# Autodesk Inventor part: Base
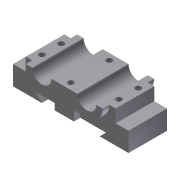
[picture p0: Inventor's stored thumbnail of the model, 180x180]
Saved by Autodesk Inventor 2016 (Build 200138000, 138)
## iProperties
Shininess: 77.0
Length Units: 11269
Angle Units: 11279
Time Units: 11290
Mass Units: 11283
Length Display Precision: 3
Angle Display Precision: 2
Created: 2002-02
Part Number: Base
Document SubType Name: Modeling
Designer: ***
Density: 1 g/cm^3
Material: Generic
Appearance: Default
Density: 0.0
Volumn: 0.0
Area: 0.0
PropertySet Name: Model Information
Control State: 0
Master: False
Checked Out: False
Author: ***
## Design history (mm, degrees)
sketch "Sketch2"
  geometry: L1 (-10.066, -1.263)-(24.934, -1.263); L2 (37.434, 11.237)-(32.434, 11.237); L3 (17.434, 11.237)-(-2.566, 11.237); L4 (-17.566, 11.237)-(-22.566, 11.237); A1 r 12.5 centre (-10.066, 11.237) between (-22.566, 11.237) and (-10.066, -1.263); A2 r 12.5 centre (24.934, 11.237) between (24.934, -1.263) and (37.434, 11.237); A3 r 7.5 centre (24.934, 11.237) between (17.434, 11.237) and (32.434, 11.237); A4 r 7.5 centre (-10.066, 11.237) between (-17.566, 11.237) and (-2.566, 11.237)
  constraints: 8 end point, 8 point on circle, 4 centre point, 3 horizontal, 3 parallel, 2 coincident, 2 equal radius, 2 tangent
  dimensions: "d0" = 12.5 radius of A1; "d1" = 7.5 radius of A4; "d2" = 35 distance of A1.centre A2.centre; "d3" = 12.5 distance between parallel lines of L3 L1
extrude "Extrusion1" new body sketch "Sketch2" stored distance "d4" = 40; taper "d5" = 0 deg
sketch "Sketch4"
  geometry: L1 (-27.566, 1.237)-(-37.566, 1.237); L2 (-37.566, 1.237)-(-37.566, -13.763); L3 (-37.566, -13.763)-(-15.066, -13.763); L4 (-15.066, -13.763)-(-20.066, -8.763); L5 (-20.066, -8.763)-(34.934, -8.763); L6 (34.934, -8.763)-(29.934, -13.763); L7 (29.934, -13.763)-(52.434, -13.763); L8 (52.434, -13.763)-(52.434, 1.237); L9 (52.434, 1.237)-(42.434, 1.237); L10 (24.934, -1.263)-(-10.066, -1.263); L11 (-17.566, 11.237)-(-22.566, 11.237) reference; L12 (37.434, 11.237)-(32.434, 11.237) reference; L13 (-22.566, 11.237)-(-27.566, 11.237); L14 (-27.566, 11.237)-(-27.566, 1.237); L15 (37.434, 11.237)-(42.434, 11.237); L16 (42.434, 11.237)-(42.434, 1.237); A1 r 12.5 centre (24.934, 11.237) between (24.934, -1.263) and (37.434, 11.237); A2 r 12.5 centre (-10.066, 11.237) between (-22.566, 11.237) and (-10.066, -1.263); A3 r 12.5 centre (24.934, 11.237) between (24.934, -1.263) and (37.434, 11.237) reference; A4 r 12.5 centre (-10.066, 11.237) between (-22.566, 11.237) and (-10.066, -1.263) reference
  constraints: 28 end point, 6 perpendicular, 5 equal length, 4 concentric, 4 parallel, 4 point on circle, 2 centre point, 2 collinear, 1 tangent
  dimensions: "d12" = 15 distance of L1.end L2.end; "d13" = 25 distance from line of L3 L11.end; "d14" = 90 distance between parallel lines of L2 L8; "d15" = 5 distance between parallel lines of L5 L7; "d16" = 22.5 distance of L2.end L3.end; "d24" = 5 distance of L12.start L15.end; "d25" = 15 distance from line of L8 L12.start
extrude "Extrusion3" join sketch "Sketch4" stored distance "d17" = 30; taper "d18" = 0 deg
sketch "Sketch5"
  geometry: L1 (-14.934, -1.263)-(0.066, -1.263); L2 (0.066, -1.263)-(0.066, -8.763); L3 (0.066, -8.763)-(-14.934, -8.763); L4 (-14.934, -8.763)-(-14.934, -1.263); L5 (10.066, -1.263)-(-24.934, -1.263) reference; 1 further point
  constraints: 8 end point, 2 parallel, 1 collinear, 1 horizontal, 1 perpendicular
  dimensions: "d19" = 7.5 distance of L1.end L2.end; "d20" = 15 distance of L2.end L3.end; "d21" = 15 distance from line of point (-29.934, -13.763) L4
extrude "Extrusion4" join sketch "Sketch5" distance "d22" = 40; taper "d23" = 0 deg
sketch "Sketch6"
  geometry: L1 (-5, -35)-(0, -35) reference; L2 (-5, -35)-(-5, -5) reference; 1 further point
  dimensions: "d26" = 7.5 distance from line of L1 point (0, -27.5); "d27" = 5 distance from line of L2 point (0, -27.5)
hole "Hole1" sketch "Sketch6" at (0, -27.5) diameter "d28" = 4.5; stored, may be unused: countersink angle "d32" = 82 deg, drill point angle "d34" = 0 deg; dims "d29" = 6, "d30" = 4, "d31" = 2, "d33" = 15
pattern_linear "Rectangular Pattern1" dims "d37" = 60, "d40" = 15
sketch "Sketch7"
  geometry: L1 (-20, -40)-(-20, -35) reference; L2 (0, -40)-(20, -40) reference; 1 further point
  dimensions: "d41" = 30 distance from line of L1 point (10, -35); "d42" = 5 distance from line of L2 point (10, -35)
hole "Hole2" sketch "Sketch7" at (10, -35) diameter "d43" = 4.5; stored, may be unused: countersink angle "d47" = 82 deg, drill point angle "d49" = 0 deg; dims "d44" = 6, "d45" = 4, "d46" = 2, "d48" = 15
pattern_linear "Rectangular Pattern2" dims "d52" = 30
body "Solid1"
